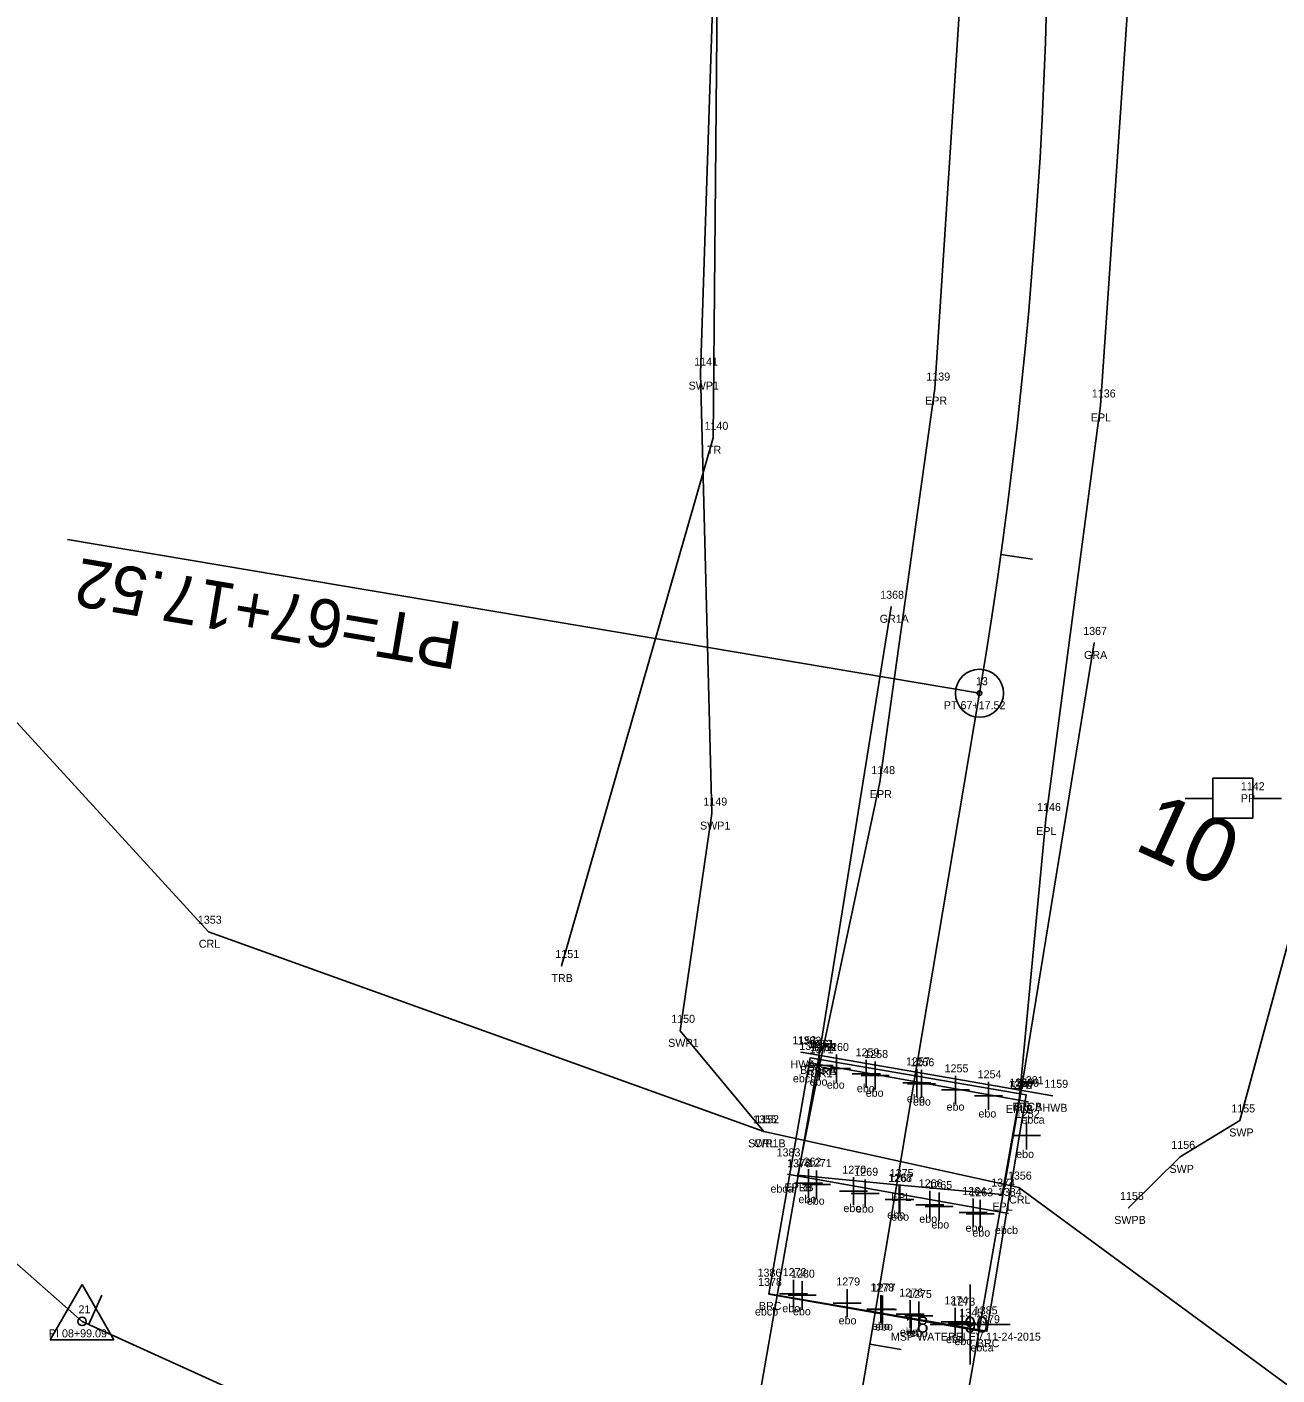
# Model space of a CAD drawing. Extents: x 2432632 to 2433497, y 684847 to 688233.
# Drawn here: x 2433028.9 to 2433185.1, y 686041.7 to 686210.1 of the extents above; entities that cross this region are included whole.
import ezdxf

# ---------------------------------------------------------------- set-up
doc = ezdxf.new("R2010")
doc.units = 0
for name, color, linetype in [('RD_EX_Bridge', 7, 'Continuous'), ('RD_EX_Bridge_txCode', 7, 'Continuous'), ('RD_EX_GuardRail', 7, 'Continuous'), ('RD_EX_GuardRail_txCode', 7, 'Continuous'), ('RD_EX_H2O', 7, 'Continuous'), ('RD_EX_H2O_txCode', 7, 'Continuous'), ('RD_EX_Misc', 7, 'Continuous'), ('RD_EX_Misc_txCode', 7, 'Continuous'), ('RD_EX_Road', 7, 'Continuous'), ('RD_EX_Road_txCode', 7, 'Continuous'), ('RD_EX_UT', 7, 'Continuous'), ('RD_EX_UT_txCode', 7, 'Continuous'), ('RD_EX_VEG', 7, 'Continuous'), ('RD_EX_VEG_txCode', 7, 'Continuous'), ('RD_HC_Cl', 7, 'Continuous'), ('RD_HC_Data', 7, 'Continuous'), ('RD_HC_Data_Tic', 7, 'Continuous'), ('RD_HC_TX_Sta50', 7, 'Continuous'), ('RD_HC_txCode', 7, 'Continuous'), ('RD_SMD_Locator', 7, 'Continuous')]:
    doc.layers.add(name, color=color, linetype=linetype)

msp = doc.modelspace()

# ---------------------------------------------------------------- linework, layer by layer
at = {"layer": 'RD_EX_Bridge'}
msp.add_line((2433125.6, 686082.01), (2433157.06, 686076.56), dxfattribs=at)
msp.add_lwpolyline([(2433153.74, 686076.69), (2433126.74, 686081.29), (2433121.59, 686051.81), (2433148.82, 686047.15), (2433153.74, 686076.69)], dxfattribs=at)
at = {"layer": 'RD_EX_GuardRail'}
for points in [[(2433136.86, 686137.66), (2433127.75, 686080.87), (2433104.3, 685946.9), (2433094.83, 685891.92)], [(2433162.23, 686133.14), (2433153.01, 686076.72), (2433129.41, 685942.33), (2433120.41, 685887.57)]]:
    msp.add_lwpolyline(points, dxfattribs=at)
at = {"layer": 'RD_EX_H2O'}
for points in [[(2433059.53, 686447.22), (2433075.46, 686410.47), (2433059.4, 686367.42), (2433076.9, 686309.73), (2433110.63, 686264.52), (2433114.63, 686215.04), (2433113.03, 686166.79), (2433114.46, 686111.82), (2433110.48, 686084.68), (2433120.95, 686072.12)], [(2433227.48, 686289.61), (2433196.85, 686279.41), (2433196.3, 686212.3), (2433190.98, 686162.16), (2433188.39, 686102.75), (2433180.42, 686073.48), (2433172.96, 686068.93), (2433166.53, 686062.55)], [(2433007.74, 686209.38), (2433001.59, 686166.41), (2433024.46, 686126.62), (2433051.58, 686097.06), (2433120.95, 686072.12), (2433152.82, 686065.09), (2433205.51, 686026.38), (2433335.15, 685993.61)]]:
    msp.add_lwpolyline(points, dxfattribs=at)
at = {"layer": 'RD_EX_Misc'}
for p, q in [((2433127.86, 686082.1), (2433127.86, 686078.6)), ((2433130.02, 686081.71), (2433130.02, 686078.21)), ((2433133.76, 686081.04), (2433133.76, 686077.54)), ((2433129.61, 686080.35), (2433126.11, 686080.35)), ((2433154.01, 686075.81), (2433126.51, 686080.74)), ((2433131.77, 686079.96), (2433128.27, 686079.96)), ((2433134.85, 686080.84), (2433134.85, 686077.34)), ((2433140.06, 686079.91), (2433140.06, 686076.41)), ((2433140.65, 686079.8), (2433140.65, 686076.3)), ((2433135.51, 686079.29), (2433132.01, 686079.29)), ((2433136.6, 686079.09), (2433133.1, 686079.09)), ((2433141.81, 686078.16), (2433138.31, 686078.16)), ((2433142.4, 686078.05), (2433138.9, 686078.05)), ((2433144.89, 686079.04), (2433144.89, 686075.54)), ((2433149.02, 686078.3), (2433149.02, 686074.8)), ((2433146.64, 686077.29), (2433143.14, 686077.29)), ((2433150.77, 686076.55), (2433147.27, 686076.55)), ((2433153.79, 686073.34), (2433153.79, 686069.84)), ((2433155.54, 686071.59), (2433152.04, 686071.59)), ((2433123.9, 686066.79), (2433151.54, 686061.85)), ((2433126.54, 686067.39), (2433126.54, 686063.89)), ((2433127.52, 686067.21), (2433127.52, 686063.71)), ((2433132.15, 686066.38), (2433132.15, 686062.88)), ((2433133.63, 686066.12), (2433133.63, 686062.62)), ((2433128.29, 686065.64), (2433124.79, 686065.64)), ((2433129.27, 686065.46), (2433125.77, 686065.46)), ((2433133.9, 686064.63), (2433130.4, 686064.63)), ((2433135.38, 686064.37), (2433131.88, 686064.37)), ((2433137.86, 686065.36), (2433137.86, 686061.86)), ((2433137.96, 686065.35), (2433137.96, 686061.85)), ((2433141.7, 686064.68), (2433141.7, 686061.18)), ((2433142.88, 686064.47), (2433142.88, 686060.97)), ((2433139.61, 686063.61), (2433136.11, 686063.61)), ((2433139.71, 686063.6), (2433136.21, 686063.6)), ((2433143.45, 686062.93), (2433139.95, 686062.93)), ((2433144.63, 686062.72), (2433141.13, 686062.72)), ((2433147.11, 686063.71), (2433147.11, 686060.21)), ((2433148, 686063.55), (2433148, 686060.05)), ((2433148.86, 686061.96), (2433145.36, 686061.96)), ((2433149.75, 686061.8), (2433146.25, 686061.8)), ((2433124.66, 686053.58), (2433124.66, 686050.08)), ((2433125.74, 686053.39), (2433125.74, 686049.89)), ((2433131.36, 686052.41), (2433131.36, 686048.91)), ((2433146.72, 686042.97), (2433146.72, 686052.97)), ((2433148.54, 686047.05), (2433121.54, 686051.76)), ((2433126.41, 686051.83), (2433122.91, 686051.83)), ((2433127.49, 686051.64), (2433123.99, 686051.64)), ((2433135.59, 686051.67), (2433135.59, 686048.17)), ((2433135.79, 686051.63), (2433135.79, 686048.13)), ((2433139.24, 686051.03), (2433139.24, 686047.53)), ((2433140.32, 686050.84), (2433140.32, 686047.34)), ((2433133.11, 686050.66), (2433129.61, 686050.66)), ((2433137.34, 686049.92), (2433133.84, 686049.92)), ((2433137.54, 686049.88), (2433134.04, 686049.88)), ((2433140.99, 686049.28), (2433137.49, 686049.28)), ((2433142.07, 686049.09), (2433138.57, 686049.09)), ((2433144.85, 686050.05), (2433144.85, 686046.55)), ((2433145.74, 686049.9), (2433145.74, 686046.4)), ((2433141.72, 686047.97), (2433151.72, 686047.97)), ((2433146.6, 686048.3), (2433143.1, 686048.3)), ((2433147.49, 686048.15), (2433143.99, 686048.15))]:
    msp.add_line(p, q, dxfattribs=at)
at = {"layer": 'RD_EX_Misc_txCode'}
for p, q in [((2433127.86, 686082.1), (2433127.86, 686078.6)), ((2433129.61, 686080.35), (2433126.11, 686080.35))]:
    msp.add_line(p, q, dxfattribs=at)
at = {"layer": 'RD_EX_Road'}
msp.add_line((2433128.09, 686081.14), (2433125.22, 686066.63), dxfattribs=at)
for points in [[(2433066.06, 686565.78), (2433098.73, 686469.74), (2433113.88, 686422.91), (2433127.93, 686372.14), (2433139.1, 686314.76), (2433144.47, 686268.02), (2433145.44, 686213), (2433142.32, 686164.92), (2433135.44, 686115.75), (2433128.09, 686081.14)], [(2433088.99, 686562.5), (2433099.45, 686534.09), (2433118.26, 686478), (2433133.83, 686430.29), (2433148.35, 686377.56), (2433159.33, 686322.19), (2433165.5, 686270.06), (2433166.43, 686212.82), (2433163.02, 686162.81), (2433156.19, 686111.14), (2433152.88, 686076.43)], [(2433152.88, 686076.43), (2433150.72, 686064.22), (2433138.04, 686065.41), (2433125.22, 686066.63)]]:
    msp.add_lwpolyline(points, dxfattribs=at)
at = {"layer": 'RD_EX_UT'}
for p, q in [((2433182.05, 686116.25), (2433177.05, 686116.25)), ((2433177.05, 686116.25), (2433177.05, 686111.25)), ((2433182.05, 686111.25), (2433182.05, 686116.25)), ((2433173.62, 686113.69), (2433177.09, 686113.69)), ((2433181.98, 686113.69), (2433185.62, 686113.69)), ((2433177.05, 686111.25), (2433182.05, 686111.25))]:
    msp.add_line(p, q, dxfattribs=at)
at = {"layer": 'RD_EX_VEG'}
msp.add_lwpolyline([(2433112.43, 688094.61), (2433041.17, 687898.89), (2432988.9, 687699.78), (2432947.96, 687578.08), (2432935.9, 687556.87), (2432944.3, 687538.7), (2432913.88, 687397.98), (2432902.4, 687330.02), (2432885.78, 687157.56), (2432894.43, 687032.93), (2432918.07, 686924.4), (2432974.73, 686759.54), (2433073.82, 686456.42), (2433099.9, 686365.23), (2433115.47, 686257.21), (2433114.64, 686158.77), (2433095.68, 686092.78)], dxfattribs=at)
at = {"layer": 'RD_HC_Cl'}
for p, q in [((2432926.72, 686144.5), (2433035.76, 686048.38)), ((2433147.9, 686126.86), (2433095.19, 685814.15)), ((2433035.76, 686048.38), (2433184.8, 685980.72))]:
    msp.add_line(p, q, dxfattribs=at)
msp.add_arc((2432536.11, 686229.97), 620.41, 350.43349, 18.81644, dxfattribs=at)
at = {"layer": 'RD_HC_Data'}
for p, q in [((2433147.9, 686126.86), (2433033.92, 686146.07)), ((2433031.79, 686046.09), (2433035.76, 686052.97)), ((2433035.76, 686052.97), (2433039.73, 686046.09)), ((2433031.79, 686046.09), (2433039.73, 686046.09))]:
    msp.add_line(p, q, dxfattribs=at)
for centre, radius in [((2433147.9, 686126.86), 3), ((2433147.9, 686126.86), 0.282), ((2433035.76, 686048.38), 0.529)]:
    msp.add_circle(centre, radius, dxfattribs=at)
at = {"layer": 'RD_HC_Data_Tic'}
for p, q in [((2433150.57, 686144.18), (2433154.53, 686143.62)), ((2433036.59, 686048.01), (2433038.24, 686051.65)), ((2433134.19, 686045.53), (2433138.13, 686044.86))]:
    msp.add_line(p, q, dxfattribs=at)
at = {"layer": 'RD_SMD_Locator'}
for centre in [(2433113.03, 686166.79), (2433142.32, 686164.92), (2433163.02, 686162.81), (2433114.64, 686158.77), (2433136.86, 686137.66), (2433162.23, 686133.14), (2433147.9, 686126.86), (2433135.44, 686115.75), (2433114.46, 686111.82), (2433156.19, 686111.14), (2433051.58, 686097.06), (2433095.68, 686092.78), (2433110.48, 686084.68), (2433125.6, 686082.01), (2433126.74, 686081.29), (2433128.09, 686081.14), (2433128.09, 686081.14), (2433127.75, 686080.87), (2433152.88, 686076.43), (2433152.88, 686076.43), (2433153.01, 686076.72), (2433153.74, 686076.69), (2433153.74, 686076.69), (2433157.06, 686076.56), (2433180.42, 686073.48), (2433120.95, 686072.12), (2433120.95, 686072.12), (2433172.96, 686068.93), (2433125.22, 686066.63), (2433125.22, 686066.63), (2433138.04, 686065.41), (2433150.72, 686064.22), (2433152.82, 686065.09), (2433166.53, 686062.55), (2433121.59, 686051.81), (2433035.76, 686048.38), (2433148.82, 686047.15)]:
    msp.add_circle(centre, 0.001, dxfattribs=at)

# ---------------------------------------------------------------- texts
at = {"layer": 'RD_EX_Bridge_txCode'}
for s, p in [('1153', (2433124.53, 686083.01)), ('1373', (2433125.39, 686082.29)), ('HWA', (2433124.29, 686080.01)), ('BRC', (2433125.48, 686079.29)), ('1366', (2433152.35, 686077.69)), ('1380', (2433152.36, 686077.69)), ('1159', (2433156, 686077.56)), ('BRCA', (2433152, 686074.69)), ('BRCB', (2433152.02, 686074.69)), ('HWB', (2433155.77, 686074.56)), ('1378', (2433120.24, 686052.81)), ('BRC', (2433120.33, 686049.81)), ('1379', (2433147.48, 686048.15)), ('BRC', (2433147.57, 686045.15))]:
    msp.add_text(s, height=1, dxfattribs=at).set_placement(p)
at = {"layer": 'RD_EX_GuardRail_txCode'}
for s, p in [('1368', (2433135.49, 686138.66)), ('GR1A', (2433135.43, 686135.66)), ('1367', (2433160.86, 686134.14)), ('GRA', (2433160.96, 686131.14)), ('1371', (2433126.68, 686081.87)), ('GR1', (2433126.8, 686078.87)), ('1369', (2433151.64, 686077.72)), ('GR', (2433152.23, 686074.72))]:
    msp.add_text(s, height=1, dxfattribs=at).set_placement(p)
at = {"layer": 'RD_EX_H2O_txCode'}
for s, p in [('1141', (2433112.25, 686167.79)), ('SWP1', (2433111.55, 686164.79)), ('1149', (2433113.4, 686112.82)), ('SWP1', (2433112.98, 686109.82)), ('1353', (2433050.23, 686098.06)), ('CRL', (2433050.35, 686095.06)), ('1150', (2433109.38, 686085.68)), ('SWP1', (2433109, 686082.68)), ('1155', (2433179.36, 686074.48)), ('1355', (2433119.6, 686073.12)), ('1152', (2433119.88, 686073.12)), ('SWP1B', (2433118.99, 686070.12)), ('CRL', (2433119.72, 686070.12)), ('1156', (2433171.87, 686069.93)), ('SWP', (2433179.11, 686071.48)), ('SWP', (2433171.64, 686066.93)), ('1356', (2433151.45, 686066.09)), ('1158', (2433165.46, 686063.55)), ('CRL', (2433151.6, 686063.09)), ('SWPB', (2433164.74, 686060.55))]:
    msp.add_text(s, height=1, dxfattribs=at).set_placement(p)
at = {"layer": 'RD_EX_Misc_txCode'}
for s, height, p in [('1382', 1, (2433125.16, 686082.94)), ('1253', 1, (2433126.51, 686082.55)), ('1261', 1, (2433126.77, 686082.55)), ('1260', 1, (2433128.61, 686082.16)), ('1259', 1, (2433132.42, 686081.49)), ('1258', 1, (2433133.5, 686081.29)), ('1257', 1, (2433138.72, 686080.36)), ('1256', 1, (2433139.28, 686080.25)), ('1255', 1, (2433143.54, 686079.49)), ('1254', 1, (2433147.67, 686078.75)), ('ebcb', 1, (2433124.58, 686078.24)), ('ebo ', 1, (2433126.67, 686077.83)), ('ebo ', 1, (2433128.82, 686077.45)), ('ebo ', 1, (2433132.58, 686077.01)), ('1381', 1, (2433152.94, 686078.01)), ('ebo ', 1, (2433133.68, 686076.44)), ('ebo ', 1, (2433138.83, 686075.72)), ('ebo ', 1, (2433139.59, 686075.34)), ('ebo ', 1, (2433143.79, 686074.7)), ('ebo ', 1, (2433147.77, 686073.85)), ('1252', 1, (2433152.44, 686073.79)), ('ebca', 1, (2433153.14, 686073.08)), ('1383', 1, (2433122.55, 686068.99)), ('ebo ', 1, (2433152.48, 686068.79)), ('1262', 1, (2433125.17, 686067.84)), ('1271', 1, (2433126.46, 686067.66)), ('1270', 1, (2433130.76, 686066.83)), ('1269', 1, (2433132.26, 686066.57)), ('1268', 1, (2433136.49, 686065.81)), ('1267', 1, (2433136.59, 686065.8)), ('1266', 1, (2433140.31, 686065.13)), ('1265', 1, (2433141.51, 686064.92)), ('ebca', 1, (2433121.78, 686064.46)), ('ebo ', 1, (2433125.28, 686063.14)), ('1264', 1, (2433145.74, 686064.16)), ('1263', 1, (2433146.63, 686064)), ('1384', 1, (2433150.19, 686064.05)), ('ebo ', 1, (2433126.32, 686062.95)), ('ebo ', 1, (2433130.9, 686062.03)), ('ebo ', 1, (2433132.45, 686061.97)), ('ebo ', 1, (2433136.37, 686061.21)), ('ebo ', 1, (2433136.87, 686060.96)), ('ebo ', 1, (2433140.38, 686060.7)), ('ebo ', 1, (2433141.89, 686059.98)), ('ebo ', 1, (2433146.16, 686059.57)), ('ebo ', 1, (2433147.01, 686058.97)), ('ebcb', 1, (2433149.82, 686059.3)), ('1386', 1, (2433120.17, 686053.96)), ('1272', 1, (2433123.31, 686054.03)), ('1280', 1, (2433124.35, 686053.84)), ('1279', 1, (2433130.01, 686052.86)), ('1278', 1, (2433134.25, 686052.12)), ('1277', 1, (2433134.44, 686052.08)), ('1276', 1, (2433137.87, 686051.48)), ('1275', 1, (2433138.97, 686051.29)), ('1274', 1, (2433143.5, 686050.5)), ('1273', 1, (2433144.39, 686050.35)), ('ebcb', 1, (2433119.84, 686049.11)), ('ebo ', 1, (2433123.26, 686049.52)), ('ebo ', 1, (2433124.59, 686049.14)), ('ebo ', 1, (2433130.3, 686048)), ('18      90', 2, (2433138.57, 686046.97)), ('1345', 1, (2433145.38, 686048.97)), ('1385', 1, (2433147.19, 686049.25)), ('ebo ', 1, (2433134.47, 686047.3)), ('ebo ', 1, (2433134.85, 686047.24)), ('ebo ', 1, (2433137.95, 686046.58)), ('ebo ', 1, (2433139.21, 686046.42)), ('MSP WATERELEV.11-24-2015', 1, (2433136.83, 686045.97)), ('ebo ', 1, (2433143.73, 686045.66)), ('ebo ', 1, (2433144.77, 686045.41)), ('ebca', 1, (2433146.77, 686044.62))]:
    msp.add_text(s, height=height, dxfattribs=at).set_placement(p)
at = {"layer": 'RD_EX_Road_txCode'}
for s, p in [('1139', (2433141.26, 686165.92)), ('EPR', (2433141.1, 686162.92)), ('1136', (2433161.94, 686163.81)), ('EPL', (2433161.82, 686160.81)), ('1148', (2433134.37, 686116.75)), ('EPR', (2433134.21, 686113.75)), ('1146', (2433155.1, 686112.14)), ('EPL', (2433154.99, 686109.14)), ('1372', (2433126.74, 686082.14)), ('1154', (2433127.02, 686082.14)), ('EPRA', (2433126.37, 686079.14)), ('EPRB', (2433126.39, 686079.14)), ('1370', (2433151.5, 686077.43)), ('1147', (2433151.82, 686077.43)), ('EPLA', (2433151.19, 686074.43)), ('EPLB', (2433151.2, 686074.43)), ('1376', (2433123.85, 686067.63)), ('1377', (2433123.88, 686067.63)), ('1375', (2433136.69, 686066.41)), ('1374', (2433149.37, 686065.22)), ('EPRB', (2433123.52, 686064.63)), ('EPLB', (2433123.55, 686064.63)), ('EPL', (2433136.84, 686063.41)), ('EPL', (2433149.51, 686062.22))]:
    msp.add_text(s, height=1, dxfattribs=at).set_placement(p)
at = {"layer": 'RD_EX_UT_txCode'}
for s, p in [('1142', (2433180.56, 686114.74)), ('PP', (2433180.56, 686113.24))]:
    msp.add_text(s, height=1, dxfattribs=at).set_placement(p)
at = {"layer": 'RD_EX_VEG_txCode'}
for s, p in [('1140', (2433113.54, 686159.77)), ('TR', (2433113.85, 686156.77)), ('1151', (2433094.9, 686093.78)), ('TRB', (2433094.41, 686090.78))]:
    msp.add_text(s, height=1, dxfattribs=at).set_placement(p)
at = {"layer": 'RD_HC_Data'}
msp.add_text('PT=67+17.52', height=6, rotation=170.4335, dxfattribs=at).set_placement((2433083.47, 686135.69))
at = {"layer": 'RD_HC_TX_Sta50'}
msp.add_text('10', height=8, rotation=335.584, dxfattribs=at).set_placement((2433167.01, 686107.41))
at = {"layer": 'RD_HC_txCode'}
for s, p in [('13', (2433147.45, 686127.86)), ('PT 67+17.52', (2433143.45, 686124.86)), ('21', (2433035.31, 686049.38)), ('PI 08+99.09', (2433031.62, 686046.38))]:
    msp.add_text(s, height=1, dxfattribs=at).set_placement(p)

doc.saveas('drawing.dxf')
